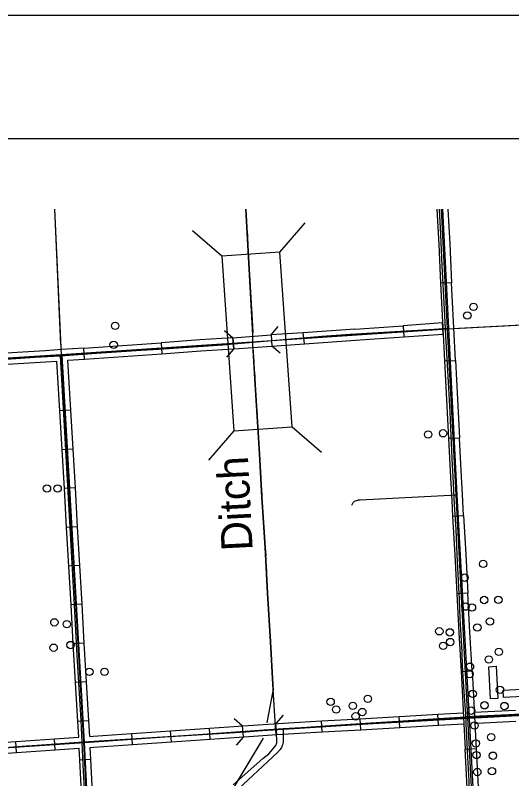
# Model space of a CAD drawing. Extents: x 646058 to 725608, y 1473014 to 1561048.
# Drawn here: x 662655 to 666031, y 1555862 to 1561048 of the extents above; entities that cross this region are included whole.
import ezdxf

# ---------------------------------------------------------------- set-up
doc = ezdxf.new("R2010")
doc.units = 0
for name, color, linetype in [('Default', 7, 'Continuous'), ('R_Border Notes', 7, 'Continuous'), ('T_Vehicle Path Rt', 7, 'Continuous')]:
    doc.layers.add(name, color=color, linetype=linetype)

msp = doc.modelspace()

# ---------------------------------------------------------------- linework, layer by layer
at = {"layer": 'Default'}
for p, q in [((664454.3, 1559438.5), (664627.5, 1559637.8)), ((664059.3, 1559410.9), (663860, 1559584.1)), ((665622.4, 1559231.4), (665547.5, 1559227.7)), ((665547.5, 1559227.7), (665559.7, 1558964.6)), ((665635.4, 1558967.7), (665622.4, 1559231.4)), ((665622.4, 1559231.4), (665622.4, 1559231.4)), ((665292.1, 1558939.2), (665297.6, 1558864.4)), ((665559.7, 1558964.6), (665561.8, 1558940)), ((665564.6, 1558883.1), (665560.3, 1558958)), ((665561.8, 1558940), (665563.2, 1558905.2)), ((664613.8, 1558891.8), (664394.7, 1558876.5)), ((664394.7, 1558876.5), (664400, 1558801.7)), ((664394.7, 1558876.5), (664394.7, 1558876.5)), ((664621.2, 1558817.1), (664613.8, 1558891.8)), ((665563.2, 1558905.2), (665564.6, 1558883.1)), ((665564.6, 1558883.1), (665574.1, 1558700.2)), ((663647.9, 1558824.2), (663653.1, 1558749.4)), ((664140.7, 1558783.5), (664135.4, 1558858.3)), ((664135.4, 1558858.3), (664140.7, 1558783.5)), ((664140.7, 1558783.5), (664135.4, 1558858.3)), ((664969.9, 1558841.5), (664969.9, 1558841.5)), ((663126.4, 1558712.6), (663121.2, 1558787.4)), ((664140.7, 1558783.5), (664140.7, 1558783.5)), ((664400, 1558801.7), (664621.2, 1558817.1)), ((663126.4, 1558712.6), (663126.4, 1558712.6)), ((665574.1, 1558700.2), (665649, 1558704.1)), ((663033.4, 1558364.9), (662958.6, 1558360.6)), ((664537.2, 1558253.4), (664736.5, 1558080.2)), ((664142.2, 1558225.8), (663969, 1558026.5)), ((665676.4, 1558176.8), (665601.5, 1558172.9)), ((663048.7, 1558101.4), (662973.8, 1558097)), ((663063.9, 1557837.8), (662989.1, 1557833.5)), ((665629.2, 1557645.6), (665704.1, 1557649.6)), ((663079.2, 1557574.3), (663004.3, 1557569.9)), ((663094.4, 1557310.7), (663019.5, 1557306.4)), ((665732.7, 1557122.4), (665657.8, 1557118.4)), ((663109.7, 1557047.1), (663034.8, 1557042.8)), ((663124.9, 1556783.6), (663050, 1556779.3)), ((665686.4, 1556591.1), (665761.3, 1556595.2)), ((663140.1, 1556520), (663065.3, 1556515.7)), ((665269.3, 1556210.3), (665265.1, 1556285.2)), ((665532.9, 1556225.3), (665528.6, 1556300.2)), ((663155.4, 1556256.5), (663080.5, 1556252.1)), ((664433, 1556162.7), (664427.8, 1556236.9)), ((664742.2, 1556180.3), (664737.9, 1556255.2)), ((665005.8, 1556195.3), (665001.5, 1556270.2)), ((663717, 1556112.3), (663711.8, 1556187.2)), ((663980.3, 1556130.6), (663975.1, 1556205.5)), ((664206.3, 1556146.4), (664201.1, 1556221.2)), ((662926.7, 1556058), (662921.7, 1556132.8)), ((663453.6, 1556094), (663448.4, 1556168.8)), ((662663.3, 1556040.4), (662658.3, 1556115.2)), ((665714.7, 1556063.9), (665789.6, 1556067.9)), ((663169.7, 1555992.6), (663094.8, 1555988.8))]:
    msp.add_line(p, q, dxfattribs=at)
for points in [[(662921.9, 1559731.1), (662966.5, 1558742.1)], [(662921.9, 1559731.1), (662963.3, 1558812.4)], [(664137.9, 1555820.3), (664339.7, 1556000.2), (664378.4, 1556030.5), (664427.1, 1556087.6), (664433, 1556107), (664433, 1556137.2), (664427.1, 1556185.2), (664406.9, 1556502.2), (664390.1, 1556792.3), (664370.8, 1557121.9), (664355.7, 1557432.1), (664332.1, 1557776), (664316.1, 1558068.7), (664286.7, 1558540.4), (664269.9, 1558809.4), (664271.6, 1558874.2), (664243, 1559365.2), (664223.4, 1559731.1)], [(664223.4, 1559731.1), (664243, 1559365.2), (664270.5, 1558893.6)], [(665522.6, 1559731.1), (665534.4, 1559491.3)], [(665536.7, 1559731.1), (665546.1, 1559559.9), (665556.3, 1559347.4), (665572.1, 1559051.5), (665577.9, 1558917.3)], [(665595.2, 1558916.1), (665553.3, 1559731.1)], [(665560.1, 1559731.1), (665600.1, 1558923.2), (665658.9, 1557791.2), (665741.1, 1556274.7), (665872.4, 1553798.2)], [(665597.7, 1559731.1), (665609.3, 1559495)], [(664231.1, 1559586.3), (664241.8, 1559388.6)], [(665609.3, 1559495), (665622.4, 1559231.4)], [(665534.4, 1559491.3), (665547.5, 1559227.7)], [(664245.5, 1559322.7), (664251.2, 1559223.8)], [(664251.2, 1559223.8), (664257, 1559125)], [(664260.8, 1559059.1), (664270.5, 1558893.6)], [(668247.5, 1559057.2), (665595.2, 1558916.1)], [(666698.3, 1558974.8), (665669.9, 1558920.1)], [(660279.4, 1557256.5), (660210.3, 1558559), (661383.8, 1558638), (662974.2, 1558739.5), (665600.1, 1558923.2)], [(664394.7, 1558876.5), (664443.9, 1558933.1)], [(664964.7, 1558916.3), (665292.1, 1558939.2)], [(665560.3, 1558958), (665292.1, 1558939.2)], [(665649, 1558704.1), (665637.5, 1558925.1), (665635.4, 1558967.7)], [(665577.9, 1558917.3), (665352.8, 1558904.3), (664932.4, 1558879.5), (664740.8, 1558865.9), (664271, 1558824.5), (664067, 1558807.2), (663631.8, 1558777.5), (663510.6, 1558770.1), (663208.3, 1558750.3), (662961.7, 1558733.6), (662787.4, 1558723.1), (662493.7, 1558703.9), (662006, 1558673), (661781.6, 1558658.2), (661529.4, 1558640.3), (661352.6, 1558629.8), (661193.7, 1558618.6), (661063.3, 1558610.6), (660798.7, 1558595.7), (660555.2, 1558579.1), (660314.7, 1558564.8), (660202.2, 1558556.2)], [(665595.2, 1558916.1), (662966.5, 1558742.1)], [(664078.8, 1558907.5), (664135.4, 1558858.3)], [(664135.4, 1558858.3), (664394.7, 1558876.5)], [(664964.7, 1558916.3), (664613.8, 1558891.8)], [(665297.6, 1558864.4), (665564.6, 1558883.1)], [(665578.1, 1558912.1), (665587.6, 1558752.3), (665598.8, 1558557.1), (665609.2, 1558352.2), (665617.6, 1558192.4), (665624.7, 1558036.7), (665632.3, 1557869.2), (665639.9, 1557726.1), (665650, 1557555.2), (665658.9, 1557383.6), (665668.9, 1557164), (665673.8, 1557080.6), (665678.6, 1556949.9), (665691.1, 1556724.9), (665694.3, 1556629.6), (665704.6, 1556452.5), (665716.3, 1556304), (665717.8, 1556283.9)], [(665732.9, 1556278.3), (665595.2, 1558916.1)], [(663384.5, 1558805.8), (663647.9, 1558824.2)], [(663911.3, 1558842.7), (663647.9, 1558824.2)], [(664135.4, 1558858.3), (663911.3, 1558842.7)], [(664621.2, 1558817.1), (664969.9, 1558841.5)], [(664969.9, 1558841.5), (665297.6, 1558864.4)], [(662858, 1558769.7), (662594.5, 1558752.9)], [(663121.2, 1558787.4), (662971.7, 1558777), (662858, 1558769.7)], [(663121.2, 1558787.4), (663384.5, 1558805.8)], [(663653.1, 1558749.4), (663916.5, 1558767.8)], [(663916.5, 1558767.8), (664140.7, 1558783.5)], [(664140.7, 1558783.5), (664091.5, 1558726.9)], [(664140.7, 1558783.5), (664400, 1558801.7)], [(664271, 1558792.6), (664286.7, 1558540.4), (664316.1, 1558068.7), (664332.1, 1557776), (664355.7, 1557432.1), (664370.8, 1557121.9), (664390.1, 1556792.3), (664406.9, 1556502.2), (664409.6, 1556459.9)], [(664271, 1558792.6), (664277.1, 1558693.8)], [(664456.6, 1558752.5), (664400, 1558801.7)], [(662966.5, 1558742.1), (660325.5, 1558577.4)], [(662961.8, 1558733.6), (662983.7, 1558337.9), (662992.1, 1558174.7), (663013.2, 1557809), (663024.9, 1557610.5), (663046.8, 1557201), (663052.7, 1557084.2), (663073.7, 1556699.9), (663100.6, 1556256.8), (663107.3, 1556108.8)], [(662966.5, 1558742.1), (663119, 1556113.2)], [(663210.9, 1553619.3), (663160.4, 1554804.7), (663162.2, 1554836.8), (663170, 1554869.1), (663176.3, 1554900.4), (663182.7, 1554928.2), (663177.2, 1555087.2), (663126.4, 1556108.9), (662974.2, 1558739.5)], [(663126.4, 1558712.6), (663389.8, 1558731)], [(663389.8, 1558731), (663653.1, 1558749.4)], [(662599.3, 1558678), (662862.8, 1558694.8)], [(662862.8, 1558694.8), (662939, 1558699.7)], [(662943.3, 1558624.2), (662939, 1558699.7)], [(663013.8, 1558704.7), (663126.4, 1558712.6)], [(663018.2, 1558628.5), (663013.8, 1558704.7)], [(665574.1, 1558700.2), (665587.8, 1558436.6)], [(665649, 1558704.1), (665662.7, 1558440.5)], [(662958.6, 1558360.6), (662943.3, 1558624.2)], [(663033.4, 1558364.9), (663018.2, 1558628.5)], [(664281.3, 1558628), (664286.7, 1558540.4), (664293.6, 1558430.3)], [(665587.8, 1558436.6), (665601.5, 1558172.9)], [(665662.7, 1558440.5), (665676.4, 1558176.8)], [(662973.8, 1558097), (662958.6, 1558360.6)], [(663048.7, 1558101.4), (663033.4, 1558364.9)], [(664297.7, 1558364.5), (664310, 1558166.9)], [(665601.5, 1558172.9), (665615.2, 1557909.3)], [(665690.1, 1557913.2), (665676.4, 1558176.8)], [(662989.1, 1557833.5), (662973.8, 1558097)], [(663063.9, 1557837.8), (663048.7, 1558101.4)], [(664314.1, 1558101), (664316.1, 1558068.7), (664325.2, 1557903.3)], [(665615.2, 1557909.3), (665623.4, 1557751.8), (665629.2, 1557645.6)], [(665704.1, 1557649.6), (665696.3, 1557793.2), (665690.1, 1557913.2)], [(663004.3, 1557569.9), (662989.1, 1557833.5)], [(663079.2, 1557574.3), (663063.9, 1557837.8)], [(664328.8, 1557837.4), (664332.1, 1557776), (664341.4, 1557639.8)], [(664943.1, 1557721.1), (664953.7, 1557738.9), (664962.5, 1557746.6), (664975.4, 1557752.4), (664988.8, 1557755.7), (665000.8, 1557757), (665658.9, 1557791.2)], [(665629.2, 1557645.6), (665643.5, 1557382)], [(665704.1, 1557649.6), (665718.4, 1557386)], [(663094.4, 1557310.7), (663079.2, 1557574.3)], [(664345.9, 1557574), (664355.7, 1557432.1), (664358.4, 1557376.4)], [(663019.5, 1557306.4), (663004.3, 1557569.9)], [(665643.5, 1557382), (665657.8, 1557118.4)], [(665718.4, 1557386), (665732.7, 1557122.4)], [(663034.8, 1557042.8), (663019.5, 1557306.4)], [(663109.7, 1557047.1), (663094.4, 1557310.7)], [(664361.6, 1557310.4), (664366.4, 1557211.5)], [(664366.4, 1557211.5), (664370.8, 1557121.9), (664371.3, 1557112.7)], [(665657.8, 1557118.4), (665672.1, 1556854.8)], [(665747, 1556858.8), (665732.7, 1557122.4)], [(663050, 1556779.3), (663034.8, 1557042.8)], [(663124.9, 1556783.6), (663109.7, 1557047.1)], [(664375.2, 1557046.8), (664386.8, 1556849.1)], [(665672.1, 1556854.8), (665686.4, 1556591.1)], [(665761.3, 1556595.2), (665747, 1556858.8)], [(663065.3, 1556515.7), (663050, 1556779.3)], [(663140.1, 1556520), (663124.9, 1556783.6)], [(664390.6, 1556783.2), (664402.1, 1556585.6)], [(665686.4, 1556591.1), (665700.7, 1556327.5), (665705.6, 1556235.1)], [(665761.3, 1556595.2), (665775.6, 1556331.6), (665780.5, 1556239.2)], [(663080.5, 1556252.1), (663065.3, 1556515.7)], [(663155.4, 1556256.5), (663140.1, 1556520)], [(664405.9, 1556519.7), (664406.9, 1556502.2), (664409.6, 1556459.9)], [(664369.1, 1556242.1), (664409.6, 1556459.9)], [(664399.3, 1556404.3), (664409.6, 1556459.9)], [(665732.9, 1556278.3), (668379.5, 1556436.3)], [(664476.5, 1556202.7), (665741.1, 1556274.7), (668379.5, 1556416.3)], [(668379.5, 1556420.5), (667910.2, 1556396.6), (667595.5, 1556382.7), (667045.2, 1556354), (666678, 1556333.2), (666494.9, 1556324.3), (666168.3, 1556305.5), (666010.9, 1556296.6), (665815, 1556286.7), (665717.8, 1556282.3)], [(664369.1, 1556242.1), (664387.2, 1556339.4)], [(665776.5, 1556314.1), (666056, 1556329.1)], [(663106.2, 1556109), (663337.2, 1556126.3), (663780.5, 1556154.5), (664223.8, 1556180.6), (664415.8, 1556195.7), (664450, 1556198.7), (664731.5, 1556219.9), (665070.3, 1556241), (665259.3, 1556254), (665461.3, 1556267.1), (665717.8, 1556282.3)], [(663119, 1556113.2), (665732.9, 1556278.3)], [(664477.1, 1556293.6), (664427.8, 1556237)], [(665001.5, 1556270.2), (665265.1, 1556285.2)], [(665265.1, 1556285.2), (665528.6, 1556300.2)], [(665528.6, 1556300.2), (665701.6, 1556310)], [(665717.8, 1556283.9), (665718.4, 1556259.5), (665720, 1556229.5), (665721.9, 1556197), (665728.5, 1556050.3), (665739, 1555845.4), (665746.6, 1555652.1), (665751.4, 1555597.3), (665758.1, 1555450), (665763.9, 1555347.2), (665768.9, 1555262.4), (665781, 1555044.3), (665786.7, 1554945), (665791.7, 1554834.5), (665812.7, 1554397.4), (665816.1, 1554300.3)], [(665870.1, 1553650.2), (665732.9, 1556278.3)], [(663086.8, 1556143.8), (663080.5, 1556252.1)], [(663161.6, 1556148.9), (663155.4, 1556256.5)], [(664144.5, 1556270.4), (664201.1, 1556221.2)], [(664238.5, 1556223.8), (664513.5, 1556242.9)], [(664513.6, 1556242.4), (664737.9, 1556255.2)], [(664737.9, 1556255.2), (665001.5, 1556270.2)], [(665269.3, 1556210.3), (665532.9, 1556225.3)], [(665532.9, 1556225.3), (665705.6, 1556235.1)], [(665705.6, 1556235.1), (665714.7, 1556063.9)], [(665780.5, 1556239.2), (665796.4, 1556240.1)], [(665780.5, 1556239.2), (665789.6, 1556067.9)], [(665796.4, 1556240.1), (666060, 1556254.2)], [(661080.3, 1555972.4), (663126.4, 1556108.9), (664476.5, 1556202.7), (664477.5, 1556111.4), (664473.4, 1556093.2), (664466.3, 1556074.5), (664457.6, 1556060.7), (664437.5, 1556041.2), (663835.5, 1555479), (663817, 1555457), (663805.5, 1555435.1), (663801.3, 1555418), (663800.3, 1555398.9), (663879.7, 1554193.6), (663889.9, 1554159.1), (663917.7, 1553666.2)], [(663448.4, 1556168.8), (663711.8, 1556187.2)], [(663711.8, 1556187.2), (663975.1, 1556205.5)], [(663975.1, 1556205.5), (664238.5, 1556223.8)], [(664433, 1556162.7), (664742.2, 1556180.3)], [(664742.2, 1556180.3), (665005.8, 1556195.3)], [(665005.8, 1556195.3), (665269.3, 1556210.3)], [(662658.3, 1556115.2), (662921.7, 1556132.8)], [(662921.7, 1556132.8), (663086.8, 1556143.8)], [(663161.6, 1556148.9), (663185, 1556150.5)], [(663185, 1556150.5), (663448.4, 1556168.8)], [(664342, 1556137.9), (664138.1, 1555798), (663784.7, 1555426.5), (663675.9, 1555231.6), (663458.5, 1554896.3), (663272.7, 1554669.7), (663254.6, 1554579.1), (663277.2, 1554126), (663354.3, 1553564.1)], [(663717, 1556112.3), (663980.3, 1556130.6)], [(663980.3, 1556130.6), (664243.7, 1556149)], [(664206.3, 1556146.4), (664157.1, 1556089.8)], [(664243.7, 1556149), (664433, 1556162.1)], [(664342, 1556137.9), (664291, 1556053)], [(660478.2, 1555921.9), (663119, 1556113.2)], [(661067.9, 1555971.8), (661783.2, 1556014.6), (662079.9, 1556036), (662280.3, 1556051.6), (662439.8, 1556064.2), (662732.6, 1556084.7), (662958.3, 1556100.2), (663106.2, 1556109)], [(662394.9, 1556097.6), (662658.3, 1556115.2)], [(662926.7, 1556058), (663090.8, 1556068.9)], [(663094.8, 1555988.8), (663090.8, 1556068.9)], [(663107.3, 1556108.8), (663114, 1555956.5)], [(663119, 1556113.2), (663245.3, 1553479.5)], [(663165.6, 1556074), (663190.2, 1556075.7)], [(663169.7, 1555992.6), (663165.6, 1556074)], [(663190.2, 1556075.7), (663453.6, 1556094)], [(663453.6, 1556094), (663717, 1556112.3)], [(662399.9, 1556022.8), (662663.3, 1556040.4)], [(662663.3, 1556040.4), (662926.7, 1556058)], [(665728.7, 1555800.3), (665714.7, 1556063.9)], [(665789.6, 1556067.9), (665803.6, 1555804.3)], [(663107.9, 1555725.1), (663094.8, 1555988.8)], [(663182.8, 1555728.9), (663169.7, 1555992.6)], [(664257.1, 1555996.4), (664155.2, 1555826.6)], [(663114, 1555956.5), (663140.1, 1555493.2), (663159.4, 1555099.7), (663168.7, 1554963.4), (663167.8, 1554929.8), (663164.5, 1554905.4), (663160.3, 1554886.1), (663156.9, 1554865.9), (663156.9, 1554843.2), (663163.6, 1554670), (663172, 1554443), (663183.8, 1554188.2), (663185.6, 1554143.9), (663186, 1554136.5)]]:
    msp.add_lwpolyline(points, dxfattribs=at)
for points in [[(664059.3, 1559410.9), (664142.2, 1558225.8), (664537.2, 1558253.4), (664454.3, 1559438.5)], [(665875.5, 1556623.4), (665925.4, 1556626.1), (665937.2, 1556407.7), (665887.3, 1556405)], [(665975.5, 1556414), (665972.8, 1556463.9), (666191.3, 1556475.8), (666194, 1556425.8)]]:
    msp.add_lwpolyline(points, close=True, dxfattribs=at)
for centre in [(665771.4, 1559067.7), (665729.2, 1559008.8), (663335.1, 1558938.3), (663324.4, 1558810.1), (665463.1, 1558200.3), (665564.2, 1558208.7), (662870.9, 1557834.2), (662943.6, 1557834.2), (665837.2, 1557321.5), (665710.1, 1557228.1), (665716.9, 1557031.4), (665844, 1557076.3), (665940.2, 1557077.6), (665760.8, 1557025.3), (665883.2, 1556931), (662921.2, 1556924.3), (663005.9, 1556912.2), (665797.2, 1556889.8), (665538.9, 1556863.9), (665609.9, 1556856.5), (663031.2, 1556770.6), (665613, 1556790.9), (662916.2, 1556752.4), (665564.4, 1556764.7), (665943, 1556724.6), (665875.7, 1556672.2), (665747.2, 1556623.4), (663159.4, 1556588.8), (663262.3, 1556588.8), (665744.7, 1556573.3), (665951.2, 1556466.3), (665765.7, 1556439.1), (664799.7, 1556384.8), (664951.1, 1556357.3), (665052.4, 1556405.1), (665846.1, 1556361.2), (665981.4, 1556356.2), (664837.1, 1556332.5), (665015, 1556315.4), (665755.2, 1556324.7), (664969.7, 1556286.2), (665777.9, 1556224.3), (665786.5, 1556102.2), (665890.8, 1556144.6), (665791.2, 1556023.1), (665903.1, 1556018.8), (665797, 1555907.7), (665896.7, 1555913.5)]:
    msp.add_circle(centre, 25, dxfattribs=at)
at = {"layer": 'R_Border Notes'}
msp.add_line((648725.4, 1560211), (716704.1, 1560211), dxfattribs=at)
at = {"layer": 'T_Vehicle Path Rt'}
msp.add_line((646059.2, 1561048.3), (717725.9, 1561048.3), dxfattribs=at)
msp.add_lwpolyline([(646057.8, 1561048.3), (717725.9, 1561048.3), (717725.9, 1515180.7), (646057.8, 1515180.7)], close=True, dxfattribs=at)

# ---------------------------------------------------------------- texts
at = {"layer": 'Default'}
msp.add_text('Ditch', height=211.2, rotation=92.9284, dxfattribs=at).set_placement((664270.1, 1557414.4))

doc.saveas('drawing.dxf')
